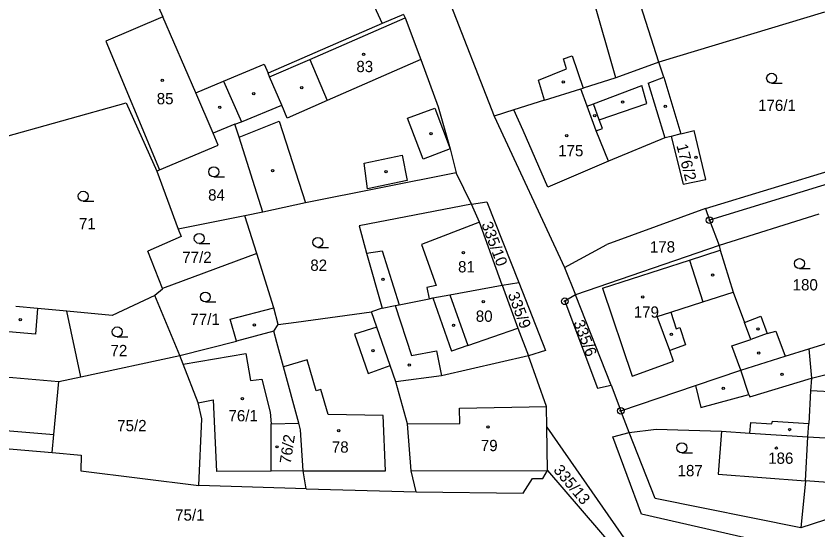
# Model space of a CAD drawing. Extents: x -762263 to -760336, y -1154405 to -1152076.
# Drawn here: x -761538.5 to -761417.7, y -1152526.7 to -1152449.2 of the extents above; entities that cross this region are included whole.
import ezdxf

# ---------------------------------------------------------------- set-up
doc = ezdxf.new("R2010")
doc.units = 0
for name, color, linetype in [('Vrstva 1', 7, 'Continuous'), ('Vrstva 18', 7, 'Continuous'), ('Vrstva 19', 7, 'Continuous'), ('Vrstva 24', 7, 'Continuous'), ('Vrstva 25', 7, 'Continuous'), ('Vrstva 4', 7, 'Continuous'), ('Vrstva 6', 7, 'Continuous')]:
    doc.layers.add(name, color=color, linetype=linetype)

msp = doc.modelspace()

# ---------------------------------------------------------------- linework, layer by layer
at = {"layer": 'Vrstva 1'}
for p, q in [((-761441.66, -1152456.18), (-761448.06, -1152435.96)), ((-761520.46, -1152440.25), (-761516.38, -1152449.36)), ((-761474.18, -1152444.55), (-761466.45, -1152464.3)), ((-761516.38, -1152449.36), (-761524.97, -1152453)), ((-761511.42, -1152460.82), (-761516.38, -1152449.36)), ((-761480.09, -1152448.97), (-761483.31, -1152450.37)), ((-761480.09, -1152448.97), (-761479.84, -1152449.52)), ((-761416.7, -1152448.65), (-761441.66, -1152456.18)), ((-761483.31, -1152450.37), (-761500.51, -1152457.83)), ((-761479.84, -1152449.52), (-761477.51, -1152455.75)), ((-761524.97, -1152453), (-761516.87, -1152472.41)), ((-761477.51, -1152455.75), (-761474.9, -1152462.92)), ((-761441.66, -1152456.18), (-761448.12, -1152458.53)), ((-761440.88, -1152458.42), (-761441.66, -1152456.18)), ((-761500.28, -1152458.39), (-761500.51, -1152457.83)), ((-761498.46, -1152462.66), (-761500.28, -1152458.39)), ((-761448.12, -1152458.53), (-761453.05, -1152460.08)), ((-761440.88, -1152458.42), (-761438.33, -1152466.97)), ((-761458.85, -1152461.91), (-761453.41, -1152460.19)), ((-761453.41, -1152460.19), (-761453.05, -1152460.08)), ((-761508.77, -1152466.88), (-761511.42, -1152460.82)), ((-761547.04, -1152469.31), (-761521.92, -1152462.31)), ((-761521.92, -1152462.31), (-761517.3, -1152472.61)), ((-761458.85, -1152461.91), (-761463.49, -1152463.37)), ((-761504.53, -1152465.15), (-761498.46, -1152462.66)), ((-761474.9, -1152462.92), (-761473.09, -1152469.26)), ((-761463.49, -1152463.37), (-761466.45, -1152464.3)), ((-761462.1, -1152466.45), (-761463.49, -1152463.37)), ((-761466.45, -1152464.3), (-761455.85, -1152487.12)), ((-761505.51, -1152465.54), (-761508.77, -1152466.88)), ((-761505.51, -1152465.54), (-761504.53, -1152465.15)), ((-761504.9, -1152467.47), (-761505.51, -1152465.54)), ((-761508.06, -1152468.69), (-761508.77, -1152466.88)), ((-761501.33, -1152478.79), (-761504.9, -1152467.47)), ((-761458.35, -1152475.01), (-761462.1, -1152466.45)), ((-761439.8, -1152467.36), (-761440.73, -1152467.56)), ((-761438.33, -1152466.97), (-761439.8, -1152467.36)), ((-761439.8, -1152467.36), (-761437.98, -1152474.58)), ((-761438.33, -1152466.97), (-761436.31, -1152466.48)), ((-761434.58, -1152473.84), (-761436.31, -1152466.48)), ((-761516.87, -1152472.41), (-761508.06, -1152468.69)), ((-761440.73, -1152467.56), (-761449.22, -1152471.1)), ((-761473.09, -1152469.26), (-761472.17, -1152472.87)), ((-761449.22, -1152471.1), (-761458.35, -1152475.01)), ((-761434.61, -1152478.25), (-761411.33, -1152471.1)), ((-761517.3, -1152472.61), (-761516.87, -1152472.41)), ((-761517.3, -1152472.61), (-761514.05, -1152481.32)), ((-761472.17, -1152472.87), (-761494.89, -1152477.39)), ((-761469.86, -1152477.57), (-761472.17, -1152472.87)), ((-761410.71, -1152472.82), (-761434.01, -1152479.98)), ((-761437.98, -1152474.58), (-761434.58, -1152473.84)), ((-761494.89, -1152477.39), (-761501.33, -1152478.79)), ((-761469.86, -1152477.57), (-761486.77, -1152480.83)), ((-761468.66, -1152480.3), (-761469.86, -1152477.57)), ((-761434.61, -1152478.25), (-761449.46, -1152483.66)), ((-761434.61, -1152478.25), (-761434.01, -1152479.98)), ((-761504, -1152479.31), (-761514.05, -1152481.32)), ((-761501.33, -1152478.79), (-761504, -1152479.31)), ((-761502.2, -1152485.03), (-761504, -1152479.31)), ((-761417.56, -1152479.08), (-761432.57, -1152483.82)), ((-761465.24, -1152489.78), (-761468.66, -1152480.3)), ((-761434.01, -1152479.98), (-761432.57, -1152483.82)), ((-761514.05, -1152481.32), (-761513.6, -1152482.44)), ((-761486.77, -1152480.83), (-761485.68, -1152484.96)), ((-761513.6, -1152482.44), (-761518.63, -1152484.68)), ((-761455.85, -1152487.12), (-761449.46, -1152483.66)), ((-761432.57, -1152483.82), (-761454.21, -1152491.25)), ((-761432.57, -1152483.82), (-761432.38, -1152484.51)), ((-761516.45, -1152490.27), (-761518.63, -1152484.68)), ((-761502.2, -1152485.03), (-761516.45, -1152490.27)), ((-761499.63, -1152493.17), (-761502.2, -1152485.03)), ((-761485.68, -1152484.96), (-761483.31, -1152493.26)), ((-761432.38, -1152484.51), (-761430.42, -1152490.82)), ((-761455.85, -1152487.12), (-761454.21, -1152491.25)), ((-761516.41, -1152490.38), (-761517.6, -1152491.33)), ((-761516.41, -1152490.38), (-761516.45, -1152490.27)), ((-761473.13, -1152491.23), (-761465.24, -1152489.78)), ((-761465.24, -1152489.78), (-761462.91, -1152496.26)), ((-761517.6, -1152491.33), (-761524, -1152494.35)), ((-761513.84, -1152500.36), (-761517.6, -1152491.33)), ((-761475.71, -1152491.7), (-761473.13, -1152491.23)), ((-761454.21, -1152491.25), (-761455.8, -1152492.21)), ((-761448.83, -1152504.87), (-761454.21, -1152491.25)), ((-761430.42, -1152490.82), (-761428.75, -1152495.4)), ((-761483.31, -1152493.26), (-761481.35, -1152492.86)), ((-761481.35, -1152492.86), (-761480.75, -1152492.74)), ((-761480.75, -1152492.74), (-761476.25, -1152491.83)), ((-761476.25, -1152491.83), (-761475.71, -1152491.7)), ((-761455.8, -1152492.21), (-761450.89, -1152505.31)), ((-761535.28, -1152493.32), (-761538.53, -1152493.01)), ((-761530.86, -1152493.72), (-761535.28, -1152493.32)), ((-761524, -1152494.35), (-761530.86, -1152493.72)), ((-761528.75, -1152503.59), (-761530.86, -1152493.72)), ((-761506.24, -1152494.88), (-761499.63, -1152493.17)), ((-761499, -1152495.69), (-761499.63, -1152493.17)), ((-761496.31, -1152495.33), (-761484.94, -1152493.82)), ((-761483.31, -1152493.26), (-761484.94, -1152493.82)), ((-761484.15, -1152496.1), (-761484.94, -1152493.82)), ((-761505.29, -1152498.22), (-761506.24, -1152494.88)), ((-761428.75, -1152495.4), (-761426.25, -1152494.43)), ((-761426.25, -1152494.43), (-761425.34, -1152497.07)), ((-761499.66, -1152496.7), (-761499, -1152495.69)), ((-761499, -1152495.69), (-761496.31, -1152495.33)), ((-761482.12, -1152501.9), (-761484.15, -1152496.1)), ((-761462.91, -1152496.26), (-761461.28, -1152500.41)), ((-761499.19, -1152498.42), (-761499.66, -1152496.7)), ((-761425.34, -1152497.07), (-761424.01, -1152496.72)), ((-761424.01, -1152496.72), (-761422.61, -1152500.49)), ((-761419.02, -1152499.36), (-761411.76, -1152497.13)), ((-761513.84, -1152500.36), (-761505.29, -1152498.22)), ((-761498.2, -1152502.08), (-761499.19, -1152498.42)), ((-761422.61, -1152500.49), (-761419.02, -1152499.36)), ((-761419.02, -1152499.36), (-761418.66, -1152503.77)), ((-761528.75, -1152503.59), (-761513.84, -1152500.36)), ((-761513.32, -1152501.7), (-761513.84, -1152500.36)), ((-761461.28, -1152500.41), (-761474.39, -1152503.43)), ((-761458.55, -1152508.07), (-761461.28, -1152500.41)), ((-761429.3, -1152502.59), (-761422.61, -1152500.49)), ((-761511.07, -1152507.5), (-761513.32, -1152501.7)), ((-761495.89, -1152510.57), (-761498.2, -1152502.08)), ((-761481.26, -1152504.34), (-761482.12, -1152501.9)), ((-761532.05, -1152504.31), (-761528.75, -1152503.59)), ((-761474.39, -1152503.43), (-761481.26, -1152504.34)), ((-761436.12, -1152504.9), (-761429.3, -1152502.59)), ((-761532.78, -1152512.26), (-761532.05, -1152504.31)), ((-761479.52, -1152510.67), (-761481.26, -1152504.34)), ((-761450.89, -1152505.31), (-761448.83, -1152504.87)), ((-761448.83, -1152504.87), (-761447.38, -1152508.7)), ((-761447.38, -1152508.7), (-761436.12, -1152504.9)), ((-761418.66, -1152503.77), (-761418.77, -1152505.69)), ((-761418.77, -1152505.69), (-761419.06, -1152510.61)), ((-761510.51, -1152509.9), (-761511.07, -1152507.5)), ((-761458.51, -1152511.17), (-761458.55, -1152508.07)), ((-761446.1, -1152511.96), (-761447.38, -1152508.7)), ((-761510.93, -1152519.96), (-761510.51, -1152509.9)), ((-761500.04, -1152510.65), (-761495.89, -1152510.57)), ((-761500.03, -1152517.8), (-761500.04, -1152510.65)), ((-761495.61, -1152511.59), (-761495.89, -1152510.57)), ((-761478.98, -1152517.74), (-761479.52, -1152510.67)), ((-761419.17, -1152512.62), (-761419.06, -1152510.61)), ((-761495.23, -1152517.78), (-761495.61, -1152511.59)), ((-761458.44, -1152517.69), (-761458.51, -1152511.17)), ((-761448.56, -1152512.64), (-761446.1, -1152511.96)), ((-761446.1, -1152511.96), (-761442.03, -1152511.48)), ((-761442.18, -1152521.92), (-761446.1, -1152511.96)), ((-761442.03, -1152511.48), (-761432.22, -1152511.79)), ((-761432.22, -1152511.79), (-761432.72, -1152518.24)), ((-761552.93, -1152513.33), (-761533.03, -1152515)), ((-761533.03, -1152515), (-761532.78, -1152512.26)), ((-761444.24, -1152524.28), (-761448.56, -1152512.64)), ((-761419.56, -1152519.24), (-761419.17, -1152512.62)), ((-761533.03, -1152515), (-761528.7, -1152515.39)), ((-761528.7, -1152515.39), (-761528.72, -1152517.77)), ((-761528.72, -1152517.77), (-761510.93, -1152519.96)), ((-761495.23, -1152517.78), (-761500.03, -1152517.8)), ((-761494.76, -1152520.45), (-761495.23, -1152517.78)), ((-761478.23, -1152520.91), (-761478.98, -1152517.74)), ((-761459.11, -1152518.89), (-761458.44, -1152517.69)), ((-761458.44, -1152517.69), (-761444.59, -1152533.75)), ((-761432.72, -1152518.24), (-761419.56, -1152519.24)), ((-761462.09, -1152521.14), (-761460.67, -1152518.92)), ((-761460.67, -1152518.92), (-761459.11, -1152518.89)), ((-761419.56, -1152519.24), (-761420.24, -1152526.35)), ((-761494.76, -1152520.45), (-761510.93, -1152519.96)), ((-761494.76, -1152520.45), (-761478.23, -1152520.91)), ((-761478.23, -1152520.91), (-761462.09, -1152521.14)), ((-761420.24, -1152526.35), (-761442.18, -1152521.92)), ((-761374.55, -1152540.13), (-761444.24, -1152524.28)), ((-761411.16, -1152523.41), (-761420.24, -1152526.35))]:
    msp.add_line(p, q, dxfattribs=at)
at = {"layer": 'Vrstva 24'}
for centre, radius in [((-761434.01, -1152479.98), 0.5), ((-761434.01, -1152479.98), 0.1), ((-761455.8, -1152492.21), 0.5), ((-761455.8, -1152492.21), 0.1), ((-761447.38, -1152508.7), 0.5), ((-761447.38, -1152508.7), 0.1)]:
    msp.add_circle(centre, radius, dxfattribs=at)
at = {"layer": 'Vrstva 25'}
for p, q in [((-761424.65, -1152459.35), (-761423.05, -1152459.35)), ((-761508.7, -1152473.45), (-761507.1, -1152473.45)), ((-761528.37, -1152477.13), (-761526.77, -1152477.13)), ((-761510.89, -1152483.49), (-761509.29, -1152483.49)), ((-761493.01, -1152484.08), (-761491.41, -1152484.08)), ((-761420.45, -1152487.28), (-761418.85, -1152487.28)), ((-761509.97, -1152492.31), (-761508.37, -1152492.31)), ((-761523.25, -1152497.57), (-761521.65, -1152497.57)), ((-761438.17, -1152515.04), (-761436.57, -1152515.04))]:
    msp.add_line(p, q, dxfattribs=at)
for centre, radius in [((-761486.13, -1152454.98), 0.175), ((-761516.46, -1152458.9), 0.175), ((-761456.05, -1152459.16), 0.175), ((-761424.65, -1152458.6), 0.75), ((-761495.45, -1152460.03), 0.175), ((-761502.67, -1152460.9), 0.175), ((-761447.11, -1152462.18), 0.175), ((-761507.79, -1152462.99), 0.175), ((-761440.68, -1152462.84), 0.175), ((-761451.29, -1152464.22), 0.175), ((-761475.95, -1152466.97), 0.175), ((-761455.52, -1152467.25), 0.175), ((-761436.05, -1152470.51), 0.175), ((-761508.7, -1152472.7), 0.75), ((-761499.85, -1152472.53), 0.175), ((-761482.74, -1152472.67), 0.175), ((-761528.37, -1152476.38), 0.75), ((-761510.89, -1152482.74), 0.75), ((-761493.01, -1152483.33), 0.75), ((-761471.09, -1152484.89), 0.175), ((-761420.45, -1152486.53), 0.75), ((-761483.21, -1152488.91), 0.175), ((-761433.55, -1152488.25), 0.175), ((-761509.97, -1152491.56), 0.75), ((-761444.06, -1152491.55), 0.175), ((-761468.1, -1152492.28), 0.175), ((-761537.87, -1152494.98), 0.175), ((-761523.25, -1152496.82), 0.75), ((-761502.58, -1152495.76), 0.175), ((-761472.58, -1152495.85), 0.175), ((-761426.72, -1152496.37), 0.175), ((-761439.74, -1152497.21), 0.175), ((-761484.73, -1152499.66), 0.175), ((-761426.59, -1152500.01), 0.175), ((-761479.25, -1152501.81), 0.175), ((-761423.07, -1152503.2), 0.175), ((-761431.93, -1152505.31), 0.175), ((-761504.38, -1152506.87), 0.175), ((-761467.39, -1152511.15), 0.175), ((-761489.88, -1152511.7), 0.175), ((-761421.93, -1152511.53), 0.175), ((-761499.17, -1152514.14), 0.175), ((-761438.17, -1152514.29), 0.75), ((-761423.92, -1152514.34), 0.175)]:
    msp.add_circle(centre, radius, dxfattribs=at)
at = {"layer": 'Vrstva 4'}
for p, q in [((-761448.12, -1152458.53), (-761452.36, -1152443.75)), ((-761485.89, -1152444.73), (-761483.31, -1152450.37)), ((-761494.23, -1152455.76), (-761479.84, -1152449.52)), ((-761456.02, -1152455.68), (-761454.68, -1152455.21)), ((-761454.68, -1152455.21), (-761453.05, -1152460.08)), ((-761507.24, -1152459.06), (-761501.11, -1152456.48)), ((-761501.11, -1152456.48), (-761500.51, -1152457.83)), ((-761500.28, -1152458.39), (-761494.23, -1152455.76)), ((-761494.23, -1152455.76), (-761491.6, -1152461.94)), ((-761477.51, -1152455.75), (-761491.6, -1152461.94)), ((-761455.58, -1152457.2), (-761456.02, -1152455.68)), ((-761459.79, -1152458.89), (-761455.58, -1152457.2)), ((-761458.85, -1152461.91), (-761459.79, -1152458.89)), ((-761443.27, -1152459.32), (-761440.88, -1152458.42)), ((-761511.42, -1152460.82), (-761507.24, -1152459.06)), ((-761507.24, -1152459.06), (-761504.53, -1152465.15)), ((-761452.46, -1152462.8), (-761453.41, -1152460.19)), ((-761451.49, -1152462.43), (-761444.22, -1152459.68)), ((-761443.46, -1152462.41), (-761444.22, -1152459.68)), ((-761443.27, -1152459.32), (-761440.73, -1152467.56)), ((-761491.6, -1152461.94), (-761497.64, -1152464.59)), ((-761452.46, -1152462.8), (-761451.49, -1152462.43)), ((-761450.64, -1152464.85), (-761451.49, -1152462.43)), ((-761450.64, -1152464.85), (-761443.46, -1152462.41)), ((-761497.64, -1152464.59), (-761498.46, -1152462.66)), ((-761479.51, -1152464.61), (-761475.38, -1152463.09)), ((-761475.38, -1152463.09), (-761473.09, -1152469.26)), ((-761451.09, -1152466.54), (-761452.46, -1152462.8)), ((-761504.9, -1152467.47), (-761498.85, -1152465.05)), ((-761498.85, -1152465.05), (-761494.89, -1152477.39)), ((-761477.17, -1152470.77), (-761479.51, -1152464.61)), ((-761450.13, -1152466.15), (-761450.64, -1152464.85)), ((-761451.09, -1152466.54), (-761450.13, -1152466.15)), ((-761449.22, -1152471.1), (-761451.09, -1152466.54)), ((-761473.09, -1152469.26), (-761477.17, -1152470.77)), ((-761486.06, -1152471.39), (-761480.34, -1152470.21)), ((-761480.34, -1152470.21), (-761479.54, -1152474)), ((-761485.52, -1152475.27), (-761486.06, -1152471.39)), ((-761479.54, -1152474), (-761485.52, -1152475.27)), ((-761468.66, -1152480.3), (-761477.39, -1152483.65)), ((-761477.39, -1152483.65), (-761475.17, -1152489.82)), ((-761485.68, -1152484.96), (-761483.33, -1152484.59)), ((-761483.33, -1152484.59), (-761480.75, -1152492.74)), ((-761437.04, -1152486.01), (-761432.38, -1152484.51)), ((-761450.11, -1152490.21), (-761437.04, -1152486.01)), ((-761437.04, -1152486.01), (-761435.02, -1152492.3)), ((-761475.17, -1152489.82), (-761476.62, -1152490.15)), ((-761476.62, -1152490.15), (-761476.25, -1152491.83)), ((-761450.11, -1152490.21), (-761445.66, -1152503.51)), ((-761473.13, -1152491.23), (-761470.41, -1152498.87)), ((-761435.02, -1152492.3), (-761430.42, -1152490.82)), ((-761481.35, -1152492.86), (-761478.89, -1152500.4)), ((-761475.71, -1152491.7), (-761472.86, -1152499.72)), ((-761439.81, -1152493.85), (-761435.02, -1152492.3)), ((-761535.28, -1152493.32), (-761535.58, -1152497.15)), ((-761441.87, -1152494.51), (-761439.81, -1152493.85)), ((-761439.81, -1152493.85), (-761439.04, -1152496.36)), ((-761440.01, -1152499.64), (-761441.87, -1152494.51)), ((-761484.15, -1152496.1), (-761487.49, -1152497.16)), ((-761470.41, -1152498.87), (-761462.91, -1152496.26)), ((-761439.04, -1152496.36), (-761438.49, -1152496.18)), ((-761438.49, -1152496.18), (-761437.65, -1152498.78)), ((-761427.78, -1152497.97), (-761428.75, -1152495.4)), ((-761535.58, -1152497.15), (-761540.78, -1152496.69)), ((-761499.66, -1152496.7), (-761505.29, -1152498.22)), ((-761487.49, -1152497.16), (-761485.46, -1152503.07)), ((-761425.34, -1152497.07), (-761427.78, -1152497.97)), ((-761470.41, -1152498.87), (-761472.86, -1152499.72)), ((-761437.65, -1152498.78), (-761440.01, -1152499.64)), ((-761430.63, -1152498.91), (-761427.78, -1152497.97)), ((-761513.32, -1152501.7), (-761503.86, -1152500.08)), ((-761503.86, -1152500.08), (-761503.17, -1152504.12)), ((-761478.89, -1152500.4), (-761475.12, -1152499.65)), ((-761475.12, -1152499.65), (-761474.39, -1152503.43)), ((-761439.43, -1152501.24), (-761440.01, -1152499.64)), ((-761429.3, -1152502.59), (-761430.63, -1152498.91)), ((-761494.63, -1152501.04), (-761498.2, -1152502.08)), ((-761493.27, -1152505.69), (-761494.63, -1152501.04)), ((-761445.66, -1152503.51), (-761439.43, -1152501.24)), ((-761485.46, -1152503.07), (-761482.12, -1152501.9)), ((-761548.33, -1152502.91), (-761532.05, -1152504.31)), ((-761428.09, -1152506.27), (-761429.3, -1152502.59)), ((-761418.66, -1152503.77), (-761414.37, -1152502.74)), ((-761503.17, -1152504.12), (-761501.46, -1152503.96)), ((-761501.46, -1152503.96), (-761500.2, -1152508.92)), ((-761436.12, -1152504.9), (-761435.29, -1152508.21)), ((-761427.94, -1152506.6), (-761418.66, -1152503.77)), ((-761492.58, -1152505.5), (-761493.27, -1152505.69)), ((-761491.47, -1152509.29), (-761492.58, -1152505.5)), ((-761414.44, -1152505.94), (-761418.77, -1152505.69)), ((-761511.07, -1152507.5), (-761508.78, -1152507.05)), ((-761508.78, -1152507.05), (-761508.31, -1152517.84)), ((-761435.29, -1152508.21), (-761428.09, -1152506.27)), ((-761428.09, -1152506.27), (-761427.94, -1152506.6)), ((-761471.69, -1152508.29), (-761458.55, -1152508.07)), ((-761471.65, -1152510.62), (-761471.69, -1152508.29)), ((-761500.2, -1152508.92), (-761500.04, -1152510.65)), ((-761483.16, -1152509.4), (-761491.47, -1152509.29)), ((-761482.81, -1152517.77), (-761483.16, -1152509.4)), ((-761552.74, -1152510.64), (-761532.78, -1152512.26)), ((-761479.52, -1152510.67), (-761471.65, -1152510.62)), ((-761427.93, -1152512.08), (-761427.79, -1152510.45)), ((-761427.79, -1152510.45), (-761424.6, -1152510.68)), ((-761424.6, -1152510.68), (-761424.53, -1152510.29)), ((-761424.53, -1152510.29), (-761419.06, -1152510.61)), ((-761432.22, -1152511.79), (-761427.93, -1152512.08)), ((-761427.93, -1152512.08), (-761419.17, -1152512.62)), ((-761419.17, -1152512.62), (-761406.79, -1152513.38)), ((-761500.03, -1152517.8), (-761508.31, -1152517.84)), ((-761495.23, -1152517.78), (-761482.81, -1152517.77)), ((-761478.98, -1152517.74), (-761458.44, -1152517.69)), ((-761406.34, -1152520.25), (-761419.56, -1152519.24))]:
    msp.add_line(p, q, dxfattribs=at)
at = {"layer": 'Vrstva 6'}
for p, q in [((-761469.86, -1152477.57), (-761467.58, -1152477.21)), ((-761467.58, -1152477.21), (-761462.72, -1152489.36)), ((-761465.24, -1152489.78), (-761462.72, -1152489.36)), ((-761462.72, -1152489.36), (-761458.71, -1152499.64)), ((-761458.71, -1152499.64), (-761461.28, -1152500.41)), ((-761458.51, -1152511.17), (-761445, -1152530.59))]:
    msp.add_line(p, q, dxfattribs=at)

# ---------------------------------------------------------------- texts
at = {"layer": 'Vrstva 18'}
for s, p in [('176/1', (-761426.687, -1152463.53)), ('84', (-761509.553, -1152477.03)), ('71', (-761529.013, -1152481.36)), ('178', (-761442.987, -1152484.86)), ('77/2', (-761513.453, -1152486.43)), ('82', (-761494.153, -1152487.62)), ('180', (-761421.477, -1152490.57)), ('77/1', (-761512.223, -1152495.77)), ('72', (-761524.263, -1152500.48)), ('75/2', (-761523.253, -1152511.79)), ('187', (-761438.817, -1152518.57)), ('75/1', (-761514.523, -1152525.26))]:
    msp.add_text(s, height=1.7, dxfattribs=at).set_placement(p)
for s, rotation, p in [('335/10', 290.4896, (-761468.408, -1152480.582)), ('335/9', 290.4896, (-761464.419, -1152491.167)), ('335/6', 291.23445, (-761454.554, -1152495.401)), ('335/13', 310.02746, (-761457.616, -1152517.694))]:
    msp.add_text(s, height=1.7, rotation=rotation, dxfattribs=at).set_placement(p)
at = {"layer": 'Vrstva 19'}
for s, p in [('83', (-761487.213, -1152457.68)), ('85', (-761517.293, -1152462.52)), ('175', (-761456.807, -1152470.36)), ('81', (-761471.893, -1152487.86)), ('80', (-761469.223, -1152495.3)), ('179', (-761445.417, -1152494.68)), ('76/1', (-761506.483, -1152510.3)), ('78', (-761490.913, -1152515.02)), ('79', (-761468.463, -1152514.79)), ('186', (-761425.167, -1152516.7))]:
    msp.add_text(s, height=1.7, dxfattribs=at).set_placement(p)
for s, rotation, p in [('176/2', 284.47354, (-761439.012, -1152468.73)), ('76/2', 81.4746, (-761497.115, -1152516.795))]:
    msp.add_text(s, height=1.7, rotation=rotation, dxfattribs=at).set_placement(p)

doc.saveas('drawing.dxf')
